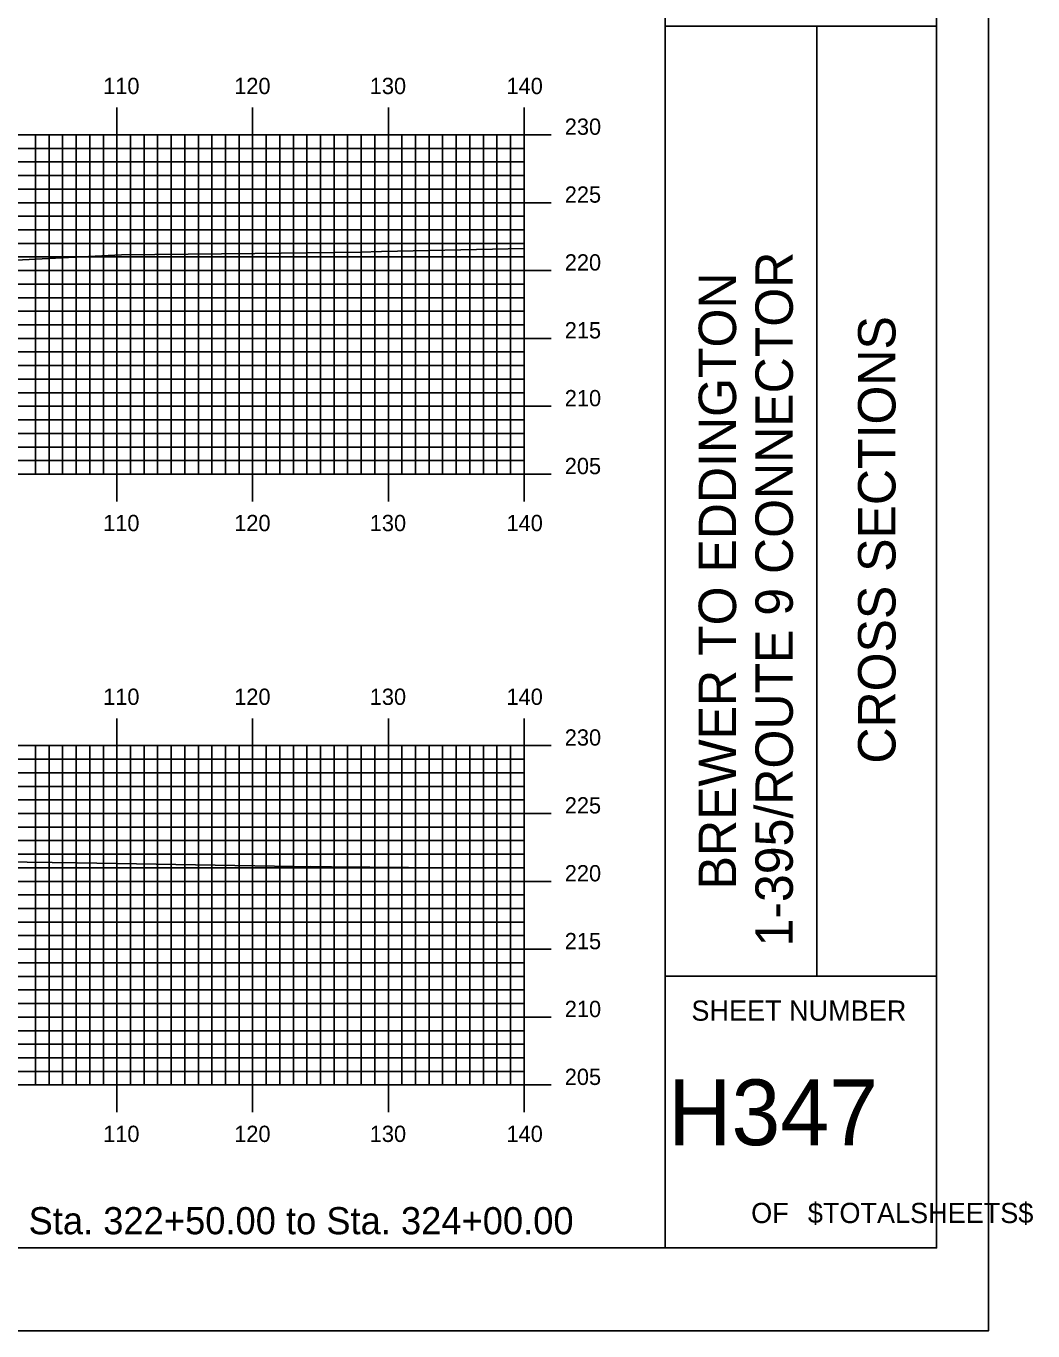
# Model space of a CAD drawing. Extents: x 1820818 to 1821161, y 442591 to 442811.
# Drawn here: x 1821087 to 1821161.2, y 442590.5 to 442686.7 of the extents above; entities that cross this region are included whole.
import ezdxf

# ---------------------------------------------------------------- set-up
doc = ezdxf.new("R2010")
doc.units = 0
for name, color, linetype in [('BORDER', 7, 'Continuous'), ('H_V ANNOTATION', 7, 'Continuous'), ('MAJOR', 7, 'Continuous'), ('MINOR', 7, 'Continuous'), ('PLOT BOUNDARY', 7, 'Continuous'), ('S_Roadway_Centerline', 7, 'Continuous')]:
    doc.layers.add(name, color=color, linetype=linetype)

msp = doc.modelspace()

# ---------------------------------------------------------------- linework, layer by layer
at = {"layer": 'BORDER'}
for p, q in [((1821134.117, 442596.665), (1821134.117, 442806.665)), ((1821134.117, 442686.671), (1821154.117, 442686.671)), ((1821145.299, 442616.671), (1821145.299, 442686.671)), ((1821134.117, 442616.671), (1821154.117, 442616.671))]:
    msp.add_line(p, q, dxfattribs=at)
msp.add_lwpolyline([(1820834.117, 442596.665), (1821154.117, 442596.665), (1821154.117, 442806.665), (1820834.117, 442806.665)], close=True, dxfattribs=at)
at = {"layer": 'MAJOR'}
for p, q in [((1821093.717, 442680.669), (1821093.717, 442678.665)), ((1821103.717, 442680.669), (1821103.717, 442678.665)), ((1821113.717, 442680.669), (1821113.717, 442678.665)), ((1821123.717, 442680.669), (1821123.717, 442678.665)), ((1820843.717, 442678.665), (1821123.717, 442678.665)), ((1820843.717, 442678.665), (1821123.717, 442678.665)), ((1821093.717, 442653.665), (1821093.717, 442678.665)), ((1821103.717, 442653.665), (1821103.717, 442678.665)), ((1821113.717, 442653.665), (1821113.717, 442678.665)), ((1821125.721, 442678.665), (1821121.713, 442678.665)), ((1821123.717, 442653.665), (1821123.717, 442678.665)), ((1821123.717, 442653.665), (1821123.717, 442678.665)), ((1820843.717, 442673.665), (1821123.717, 442673.665)), ((1821125.721, 442673.665), (1821121.713, 442673.665)), ((1820843.717, 442668.665), (1821123.717, 442668.665)), ((1821125.721, 442668.665), (1821121.713, 442668.665)), ((1820843.717, 442663.665), (1821123.717, 442663.665)), ((1821125.721, 442663.665), (1821121.713, 442663.665)), ((1820843.717, 442658.665), (1821123.717, 442658.665)), ((1821125.721, 442658.665), (1821121.713, 442658.665)), ((1820843.717, 442653.665), (1821123.717, 442653.665)), ((1820843.717, 442653.665), (1821123.717, 442653.665)), ((1821093.717, 442651.661), (1821093.717, 442653.665)), ((1821103.717, 442651.661), (1821103.717, 442653.665)), ((1821113.717, 442651.661), (1821113.717, 442653.665)), ((1821125.721, 442653.665), (1821121.713, 442653.665)), ((1821123.717, 442651.661), (1821123.717, 442653.665)), ((1821093.717, 442635.669), (1821093.717, 442633.665)), ((1821103.717, 442635.669), (1821103.717, 442633.665)), ((1821113.717, 442635.669), (1821113.717, 442633.665)), ((1821123.717, 442635.669), (1821123.717, 442633.665)), ((1820843.717, 442633.665), (1821123.717, 442633.665)), ((1820843.717, 442633.665), (1821123.717, 442633.665)), ((1821093.717, 442608.665), (1821093.717, 442633.665)), ((1821103.717, 442608.665), (1821103.717, 442633.665)), ((1821113.717, 442608.665), (1821113.717, 442633.665)), ((1821125.721, 442633.665), (1821121.713, 442633.665)), ((1821123.717, 442608.665), (1821123.717, 442633.665)), ((1821123.717, 442608.665), (1821123.717, 442633.665)), ((1820843.717, 442628.665), (1821123.717, 442628.665)), ((1821125.721, 442628.665), (1821121.713, 442628.665)), ((1820843.717, 442623.665), (1821123.717, 442623.665)), ((1821125.721, 442623.665), (1821121.713, 442623.665)), ((1820843.717, 442618.665), (1821123.717, 442618.665)), ((1821125.721, 442618.665), (1821121.713, 442618.665)), ((1820843.717, 442613.665), (1821123.717, 442613.665)), ((1821125.721, 442613.665), (1821121.713, 442613.665)), ((1820843.717, 442608.665), (1821123.717, 442608.665)), ((1820843.717, 442608.665), (1821123.717, 442608.665)), ((1821093.717, 442606.661), (1821093.717, 442608.665)), ((1821103.717, 442606.661), (1821103.717, 442608.665)), ((1821113.717, 442606.661), (1821113.717, 442608.665)), ((1821125.721, 442608.665), (1821121.713, 442608.665)), ((1821123.717, 442606.661), (1821123.717, 442608.665))]:
    msp.add_line(p, q, dxfattribs=at)
at = {"layer": 'MINOR'}
for p, q in [((1821087.717, 442653.665), (1821087.717, 442678.665)), ((1821088.717, 442653.665), (1821088.717, 442678.665)), ((1821089.717, 442653.665), (1821089.717, 442678.665)), ((1821090.717, 442653.665), (1821090.717, 442678.665)), ((1821091.717, 442653.665), (1821091.717, 442678.665)), ((1821092.717, 442653.665), (1821092.717, 442678.665)), ((1821094.717, 442653.665), (1821094.717, 442678.665)), ((1821095.717, 442653.665), (1821095.717, 442678.665)), ((1821096.717, 442653.665), (1821096.717, 442678.665)), ((1821097.717, 442653.665), (1821097.717, 442678.665)), ((1821098.717, 442653.665), (1821098.717, 442678.665)), ((1821099.717, 442653.665), (1821099.717, 442678.665)), ((1821100.717, 442653.665), (1821100.717, 442678.665)), ((1821101.717, 442653.665), (1821101.717, 442678.665)), ((1821102.717, 442653.665), (1821102.717, 442678.665)), ((1821104.717, 442653.665), (1821104.717, 442678.665)), ((1821105.717, 442653.665), (1821105.717, 442678.665)), ((1821106.717, 442653.665), (1821106.717, 442678.665)), ((1821107.717, 442653.665), (1821107.717, 442678.665)), ((1821108.717, 442653.665), (1821108.717, 442678.665)), ((1821109.717, 442653.665), (1821109.717, 442678.665)), ((1821110.717, 442653.665), (1821110.717, 442678.665)), ((1821111.717, 442653.665), (1821111.717, 442678.665)), ((1821112.717, 442653.665), (1821112.717, 442678.665)), ((1821114.717, 442653.665), (1821114.717, 442678.665)), ((1821115.717, 442653.665), (1821115.717, 442678.665)), ((1821116.717, 442653.665), (1821116.717, 442678.665)), ((1821117.717, 442653.665), (1821117.717, 442678.665)), ((1821118.717, 442653.665), (1821118.717, 442678.665)), ((1821119.717, 442653.665), (1821119.717, 442678.665)), ((1821120.717, 442653.665), (1821120.717, 442678.665)), ((1821121.717, 442653.665), (1821121.717, 442678.665)), ((1821122.717, 442653.665), (1821122.717, 442678.665)), ((1820843.717, 442677.665), (1821123.717, 442677.665)), ((1821123.717, 442677.665), (1821121.713, 442677.665)), ((1820843.717, 442676.665), (1821123.717, 442676.665)), ((1821123.717, 442676.665), (1821121.713, 442676.665)), ((1820843.717, 442675.665), (1821123.717, 442675.665)), ((1821123.717, 442675.665), (1821121.713, 442675.665)), ((1820843.717, 442674.665), (1821123.717, 442674.665)), ((1821123.717, 442674.665), (1821121.713, 442674.665)), ((1820843.717, 442672.665), (1821123.717, 442672.665)), ((1821123.717, 442672.665), (1821121.713, 442672.665)), ((1820843.717, 442671.665), (1821123.717, 442671.665)), ((1821123.717, 442671.665), (1821121.713, 442671.665)), ((1820843.717, 442670.665), (1821123.717, 442670.665)), ((1821123.717, 442670.665), (1821121.713, 442670.665)), ((1820843.717, 442669.665), (1821123.717, 442669.665)), ((1821123.717, 442669.665), (1821121.713, 442669.665)), ((1820843.717, 442667.665), (1821123.717, 442667.665)), ((1821123.717, 442667.665), (1821121.713, 442667.665)), ((1820843.717, 442666.665), (1821123.717, 442666.665)), ((1821123.717, 442666.665), (1821121.713, 442666.665)), ((1820843.717, 442665.665), (1821123.717, 442665.665)), ((1821123.717, 442665.665), (1821121.713, 442665.665)), ((1820843.717, 442664.665), (1821123.717, 442664.665)), ((1821123.717, 442664.665), (1821121.713, 442664.665)), ((1820843.717, 442662.665), (1821123.717, 442662.665)), ((1821123.717, 442662.665), (1821121.713, 442662.665)), ((1820843.717, 442661.665), (1821123.717, 442661.665)), ((1821123.717, 442661.665), (1821121.713, 442661.665)), ((1820843.717, 442660.665), (1821123.717, 442660.665)), ((1821123.717, 442660.665), (1821121.713, 442660.665)), ((1820843.717, 442659.665), (1821123.717, 442659.665)), ((1821123.717, 442659.665), (1821121.713, 442659.665)), ((1820843.717, 442657.665), (1821123.717, 442657.665)), ((1821123.717, 442657.665), (1821121.713, 442657.665)), ((1820843.717, 442656.665), (1821123.717, 442656.665)), ((1821123.717, 442656.665), (1821121.713, 442656.665)), ((1820843.717, 442655.665), (1821123.717, 442655.665)), ((1821123.717, 442655.665), (1821121.713, 442655.665)), ((1820843.717, 442654.665), (1821123.717, 442654.665)), ((1821123.717, 442654.665), (1821121.713, 442654.665)), ((1821087.717, 442608.665), (1821087.717, 442633.665)), ((1821088.717, 442608.665), (1821088.717, 442633.665)), ((1821089.717, 442608.665), (1821089.717, 442633.665)), ((1821090.717, 442608.665), (1821090.717, 442633.665)), ((1821091.717, 442608.665), (1821091.717, 442633.665)), ((1821092.717, 442608.665), (1821092.717, 442633.665)), ((1821094.717, 442608.665), (1821094.717, 442633.665)), ((1821095.717, 442608.665), (1821095.717, 442633.665)), ((1821096.717, 442608.665), (1821096.717, 442633.665)), ((1821097.717, 442608.665), (1821097.717, 442633.665)), ((1821098.717, 442608.665), (1821098.717, 442633.665)), ((1821099.717, 442608.665), (1821099.717, 442633.665)), ((1821100.717, 442608.665), (1821100.717, 442633.665)), ((1821101.717, 442608.665), (1821101.717, 442633.665)), ((1821102.717, 442608.665), (1821102.717, 442633.665)), ((1821104.717, 442608.665), (1821104.717, 442633.665)), ((1821105.717, 442608.665), (1821105.717, 442633.665)), ((1821106.717, 442608.665), (1821106.717, 442633.665)), ((1821107.717, 442608.665), (1821107.717, 442633.665)), ((1821108.717, 442608.665), (1821108.717, 442633.665)), ((1821109.717, 442608.665), (1821109.717, 442633.665)), ((1821110.717, 442608.665), (1821110.717, 442633.665)), ((1821111.717, 442608.665), (1821111.717, 442633.665)), ((1821112.717, 442608.665), (1821112.717, 442633.665)), ((1821114.717, 442608.665), (1821114.717, 442633.665)), ((1821115.717, 442608.665), (1821115.717, 442633.665)), ((1821116.717, 442608.665), (1821116.717, 442633.665)), ((1821117.717, 442608.665), (1821117.717, 442633.665)), ((1821118.717, 442608.665), (1821118.717, 442633.665)), ((1821119.717, 442608.665), (1821119.717, 442633.665)), ((1821120.717, 442608.665), (1821120.717, 442633.665)), ((1821121.717, 442608.665), (1821121.717, 442633.665)), ((1821122.717, 442608.665), (1821122.717, 442633.665)), ((1820843.717, 442632.665), (1821123.717, 442632.665)), ((1821123.717, 442632.665), (1821121.713, 442632.665)), ((1820843.717, 442631.665), (1821123.717, 442631.665)), ((1821123.717, 442631.665), (1821121.713, 442631.665)), ((1820843.717, 442630.665), (1821123.717, 442630.665)), ((1821123.717, 442630.665), (1821121.713, 442630.665)), ((1820843.717, 442629.665), (1821123.717, 442629.665)), ((1821123.717, 442629.665), (1821121.713, 442629.665)), ((1820843.717, 442627.665), (1821123.717, 442627.665)), ((1821123.717, 442627.665), (1821121.713, 442627.665)), ((1820843.717, 442626.665), (1821123.717, 442626.665)), ((1821123.717, 442626.665), (1821121.713, 442626.665)), ((1820843.717, 442625.665), (1821123.717, 442625.665)), ((1821123.717, 442625.665), (1821121.713, 442625.665)), ((1820843.717, 442624.665), (1821123.717, 442624.665)), ((1821123.717, 442624.665), (1821121.713, 442624.665)), ((1820843.717, 442622.665), (1821123.717, 442622.665)), ((1821123.717, 442622.665), (1821121.713, 442622.665)), ((1820843.717, 442621.665), (1821123.717, 442621.665)), ((1821123.717, 442621.665), (1821121.713, 442621.665)), ((1820843.717, 442620.665), (1821123.717, 442620.665)), ((1821123.717, 442620.665), (1821121.713, 442620.665)), ((1820843.717, 442619.665), (1821123.717, 442619.665)), ((1821123.717, 442619.665), (1821121.713, 442619.665)), ((1820843.717, 442617.665), (1821123.717, 442617.665)), ((1821123.717, 442617.665), (1821121.713, 442617.665)), ((1820843.717, 442616.665), (1821123.717, 442616.665)), ((1821123.717, 442616.665), (1821121.713, 442616.665)), ((1820843.717, 442615.665), (1821123.717, 442615.665)), ((1821123.717, 442615.665), (1821121.713, 442615.665)), ((1820843.717, 442614.665), (1821123.717, 442614.665)), ((1821123.717, 442614.665), (1821121.713, 442614.665)), ((1820843.717, 442612.665), (1821123.717, 442612.665)), ((1821123.717, 442612.665), (1821121.713, 442612.665)), ((1820843.717, 442611.665), (1821123.717, 442611.665)), ((1821123.717, 442611.665), (1821121.713, 442611.665)), ((1820843.717, 442610.665), (1821123.717, 442610.665)), ((1821123.717, 442610.665), (1821121.713, 442610.665)), ((1820843.717, 442609.665), (1821123.717, 442609.665)), ((1821123.717, 442609.665), (1821121.713, 442609.665))]:
    msp.add_line(p, q, dxfattribs=at)
at = {"layer": 'PLOT BOUNDARY'}
msp.add_lwpolyline([(1820817.93, 442590.547), (1821157.93, 442590.547), (1821157.93, 442810.547), (1820817.93, 442810.547)], close=True, dxfattribs=at)
at = {"layer": 'S_Roadway_Centerline'}
for points in [[(1821009.437, 442670.252), (1821021.978, 442670.008), (1821029.676, 442669.872), (1821043.901, 442669.845), (1821056.274, 442669.644), (1821060.771, 442669.769), (1821069.309, 442669.278), (1821077.78, 442669.268), (1821083.32, 442669.276), (1821094.051, 442669.83), (1821103.872, 442669.929), (1821111.66, 442670.028), (1821113.217, 442670.079), (1821123.717, 442670.297)], [(1821014.126, 442625.623), (1821023.163, 442625.591), (1821039.611, 442625.441), (1821040.758, 442625.408), (1821041.415, 442625.407), (1821043.729, 442625.399), (1821056.429, 442625.294), (1821066.724, 442625.147), (1821073.701, 442625.024), (1821081.532, 442625.143), (1821090.793, 442625.035), (1821106.787, 442624.768), (1821107.541, 442624.739), (1821107.967, 442624.753), (1821109.525, 442624.738), (1821120.883, 442624.627), (1821123.717, 442624.667)]]:
    msp.add_lwpolyline(points, dxfattribs=at)

# ---------------------------------------------------------------- texts
at = {"layer": 'BORDER'}
for s, p in [('1-395/ROUTE 9 CONNECTOR', (1821143.521, 442618.865)), ('BREWER TO EDDINGTON', (1821139.341, 442623.074)), ('CROSS SECTIONS', (1821151.086, 442632.339))]:
    msp.add_text(s, height=2.75575, rotation=90, dxfattribs=at).set_placement(p)
for s, height, p in [('SHEET NUMBER', 1.49054, (1821136.048, 442613.398)), ('H347', 4.8388, (1821134.327, 442604.23)), ('OF', 1.4905, (1821140.451, 442598.491)), ('$TOTALSHEETS$', 1.49054, (1821144.63, 442598.491))]:
    msp.add_text(s, height=height, dxfattribs=at).set_placement(p)
at = {"layer": 'H_V ANNOTATION'}
for s, height, p in [('110', 1.2, (1821092.7, 442681.665)), ('120', 1.2, (1821102.358, 442681.665)), ('130', 1.2, (1821112.347, 442681.665)), ('140', 1.2, (1821122.422, 442681.665)), ('230', 1.2, (1821126.717, 442678.665)), ('225', 1.2, (1821126.717, 442673.665)), ('220', 1.2, (1821126.717, 442668.665)), ('215', 1.2, (1821126.717, 442663.665)), ('210', 1.2, (1821126.717, 442658.665)), ('205', 1.2, (1821126.717, 442653.665)), ('110', 1.2, (1821092.7, 442649.465)), ('120', 1.2, (1821102.358, 442649.465)), ('130', 1.2, (1821112.347, 442649.465)), ('140', 1.2, (1821122.422, 442649.465)), ('110', 1.2, (1821092.7, 442636.665)), ('120', 1.2, (1821102.358, 442636.665)), ('130', 1.2, (1821112.347, 442636.665)), ('140', 1.2, (1821122.422, 442636.665)), ('230', 1.2, (1821126.717, 442633.665)), ('225', 1.2, (1821126.717, 442628.665)), ('220', 1.2, (1821126.717, 442623.665)), ('215', 1.2, (1821126.717, 442618.665)), ('210', 1.2, (1821126.717, 442613.665)), ('205', 1.2, (1821126.717, 442608.665)), ('110', 1.2, (1821092.7, 442604.465)), ('120', 1.2, (1821102.358, 442604.465)), ('130', 1.2, (1821112.347, 442604.465)), ('140', 1.2, (1821122.422, 442604.465)), ('Sta. 322+50.00 to Sta. 324+00.00', 2.0004, (1821087.208, 442597.665))]:
    msp.add_text(s, height=height, dxfattribs=at).set_placement(p)

doc.saveas('drawing.dxf')
